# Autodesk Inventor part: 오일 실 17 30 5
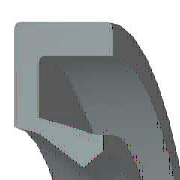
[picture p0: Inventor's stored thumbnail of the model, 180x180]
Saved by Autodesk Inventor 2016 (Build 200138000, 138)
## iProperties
Created: 2012-02
Part Number: 오일 실 17 30 5
Material: 고무
Description: 오일 실 - 스프링 장착, 비스프링, 고무 덮개 G
Document SubType Name: Modeling
Standard: JIS B 2402
Designer: mduedu
Standards Organization: JIS
Language: ko-KR
Size Designation: 17 30 5 A
Categories: <MemberInstance><Categories><Category DisplayName="샤프트 부품" InternalName="7f7aeb1f-a693-4053-b835-cee3144e0d98" Mnemonic="SHFT"><Category DisplayName="실링" Intern
Density: 0.93 g/cm^3
Appearance: 고무 - 검은색 - 버전 1.1
IsCustomPart: 1
Author: mduedu
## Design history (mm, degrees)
body "Solid1"
revolve "회전1" stored, may be unused: angle "d29" = 360 deg
chamfer "모따기1" distance "d30" = 0.25 (= 0.05 x b); stored, may be unused: second distance "d31" = 0.5 (= 0.1 x b), angle "d39" = 45 deg
chamfer "모따기2" distance "d32" = 0.5 (= 0.1 x b); stored, may be unused: second distance "d33" = 0.25 (= 0.05 x b), angle "d40" = 45 deg
fillet "모깎기1" dims "d34" = 0.25 (= 0.05 x b)
sketch "스케치2"
  geometry: L1 (9.58, -3.438)-(9.905, -5); L2 (9.147, -3.282)-(9.58, -3.438); L3 (8.5, -1.72)-(9.147, -3.282); L4 (9.682, -1.22)-(8.5, -1.72); L5 (10.811, -3.75)-(9.682, -1.22); L6 (12.111, -3.75)-(10.811, -3.75); L7 (13.556, -1.25)-(12.111, -3.75); L8 (13.556, 0)-(13.556, -1.25); L9 (15, 0)-(13.556, 0); L10 (15, -5)-(15, 0); L11 (9.905, -5)-(15, -5); L12 (0, -9.6)-(0, 1.6) reference; L13 (28, 0)-(14, 0) reference
  constraints: 22 end point, 3 horizontal, 2 vertical
  dimensions: "d2" = 5 distance of L10.start L9.start (= b); "d4" = 1.25 vertical distance of L5.start L1.end (= 0.25 x b); "d6" = 1.44444 distance of L9.start L8.start (= 0.111111 x dd - 0.111111 x Diam); "d8" = 1.25 distance of L8.start L7.start (= 0.25 x b); "d10" = 1.44444 horizontal distance of L7.start L6.start (= 0.111111 x dd - 0.111111 x Diam); "d12" = 1.21951 vertical distance of L9.start L4.start (= 0.243902 x b); "d14" = 1.18182 horizontal distance of L4.start L3.start (= 0.0909091 x dd - 0.0909091 x Diam); "d16" = 0.5 vertical distance of L4.start L3.start (= 0.1 x b); "d18" = 1.3 distance of L6.start L5.start (= 0.1 x dd - 0.1 x Diam); "d20" = 1.5625 vertical distance of L3.start L2.start (= 0.3125 x b); "d22" = 0.64677 horizontal distance of L3.start L2.start (= 0.0497512 x dd - 0.0497512 x Diam); "d24" = 0.325 horizontal distance of L1.start L1.end (= 0.025 x dd - 0.025 x Diam); "d26" = 1.5625 vertical distance of L1.start L1.end (= 0.3125 x b); "d28" = 0.43333 horizontal distance of L2.start L1.start (= 0.0333333 x dd - 0.0333333 x Diam); "d35" = 0 distance between parallel lines of L13 L9; "d36" = 15 distance between parallel lines of L12 L10 (= 0.5 x dd); "d37" = 8.5 distance from line of L12 L3.start (= 0.5 x Diam)
other parameters: "Diam" = 17 [user parameter; used in 8 equation terms], "b" = 5 [user parameter; used in 12 equation terms], "d1" = 8 (derived), "d3" = 2 (derived), "d5" = 2.22222 (derived), "d7" = 2 (derived), "d9" = 2.22222 (derived), "d11" = 1.95122 (derived), "d13" = 1.81818 (derived), "d15" = 0.8 (derived), "d17" = 2 (derived), "d19" = 2.5 (derived), "d21" = 0.99502 (derived), "d23" = 0.5 (derived), "d25" = 2.5 (derived), "d27" = 0.66667 (derived), "d38" = 0
